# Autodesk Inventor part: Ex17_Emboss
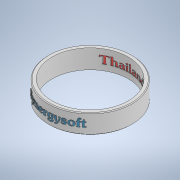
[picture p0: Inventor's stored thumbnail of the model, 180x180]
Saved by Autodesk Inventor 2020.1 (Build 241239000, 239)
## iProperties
Created: 2019-11
Part Number: Ex17_Emboss
Material: Generic
Document SubType Name: Modeling
Designer: Synergysoft Dell02
Density: 1 g/cm^3
Appearance: Default
Author: Synergysoft Dell02
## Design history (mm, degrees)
sketch "Sketch1"
  geometry: C1 r 10 at (0, 0); C2 r 11 at (0, 0); 1 further point
  constraints: 2 centre point, 2 coincident
  dimensions: "d0" = 20 diameter of C1; "d1" = 22 diameter of C2
extrude "Extrusion1" new body sketch "Sketch1" distance "d2" = 5; taper "d3" = 0 deg
chamfer "Chamfer1" distance "d4" = 0.2; stored, may be unused: second distance "d5" = 2, angle "d6" = 45 deg
sketch "Sketch2"
  geometry: L1 (-9, 4)-(9, 4); L2 (9, 4)-(9, 1); L3 (9, 1)-(-9, 1); L4 (-9, 1)-(-9, 4); L5 (10, 5)-(10, 0) reference; 4 further points
  constraints: 3 midpoint, 1 horizontal alignment, 1 vertical alignment, 2 other
  dimensions: "d7" = 3 distance of L1.end L2.end; "d8" = 18 distance of L2.end L3.end
emboss "Emboss1" sketch "Sketch2" dims "d9" = 0.1, "d10" = 0
workplane "Work Plane1"
sketch "Sketch3"
  geometry: L1 (-9, 4)-(9, 4); L2 (9, 4)-(9, 1); L3 (9, 1)-(-9, 1); L4 (-9, 1)-(-9, 4); L5 (11, 0.2)-(11, 4.8) reference; 4 further points
  constraints: 3 midpoint, 1 horizontal alignment, 1 vertical alignment, 2 other
  dimensions: "d11" = 3 distance of L1.end L2.end; "d12" = 18 distance of L2.end L3.end
emboss "Emboss2" sketch "Sketch3" dims "d13" = 0.1, "d14" = 0
body "Solid1"
